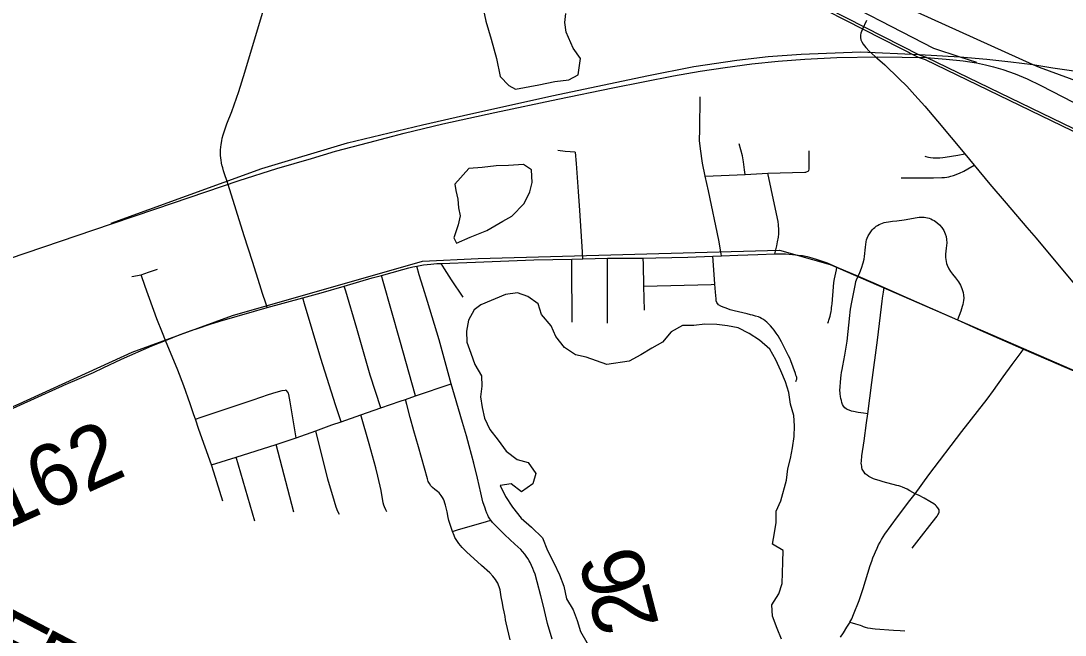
# Model space of a CAD drawing. Extents: x 0 to 34, y 0 to 22.
# Drawn here: x 3.607 to 4.562, y 14.566 to 15.128 of the extents above; entities that cross this region are included whole.
import ezdxf

# ---------------------------------------------------------------- set-up
doc = ezdxf.new("R2010")
doc.units = 0
for name, color, linetype in [('GM_X_County_Road', 7, 'Continuous'), ('GM_X_County_Road_Text', 7, 'Continuous'), ('GM_X_Major_Lake', 7, 'Continuous'), ('GM_X_Minor_Lake', 7, 'Continuous'), ('GM_X_Rail_Line', 7, 'Continuous'), ('GM_X_Township_Road', 7, 'Continuous'), ('GM_X_Township_Road_Text', 7, 'Continuous')]:
    doc.layers.add(name, color=color, linetype=linetype)

msp = doc.modelspace()

# ---------------------------------------------------------------- linework, layer by layer
at = {"layer": 'GM_X_County_Road'}
for p, q in [((4.47048, 15.00593), (4.47909, 14.99559)), ((4.11119, 14.90945), (4.1212, 14.90973)), ((4.1212, 14.90973), (4.14376, 14.91036)), ((4.24024, 14.91223), (4.24809, 14.91252)), ((4.35362, 14.9022), (4.37305, 14.89396)), ((3.83265, 14.86521), (3.86518, 14.87421))]:
    msp.add_line(p, q, dxfattribs=at)
for points in [[(3.79142, 14.99481), (3.79119, 14.99568), (3.79081, 14.99776), (3.79038, 15.00004), (3.79017, 15.00236), (3.78998, 15.00446), (3.78999, 15.00705), (3.78999, 15.00951), (3.79014, 15.0119), (3.79046, 15.01455), (3.79106, 15.01773), (3.79151, 15.02013), (3.79238, 15.02325), (3.79319, 15.02618), (3.79571, 15.03324), (3.80011, 15.04462), (3.80658, 15.06305), (3.81213, 15.08062), (3.82285, 15.11626), (3.83435, 15.155)], [(4.38074, 15.12777), (4.37658, 15.11939), (4.37548, 15.11633), (4.37516, 15.11435), (4.37517, 15.11233), (4.37557, 15.11034), (4.37632, 15.10847), (4.37767, 15.10622), (4.37872, 15.1048), (4.38004, 15.10321), (4.38306, 15.09997), (4.38863, 15.0949), (4.39079, 15.093)], [(4.39079, 15.093), (4.39729, 15.08728), (4.41037, 15.07499), (4.41749, 15.06777), (4.42482, 15.05954), (4.43393, 15.04946), (4.44559, 15.03592), (4.47048, 15.00593)], [(3.83265, 14.86521), (3.83123, 14.86942), (3.82833, 14.87803), (3.82579, 14.88618), (3.81911, 14.90734), (3.81157, 14.93103), (3.79688, 14.97783), (3.79265, 14.99021), (3.79189, 14.99307), (3.79142, 14.99481)], [(4.47909, 14.99559), (4.49344, 14.97805), (4.50846, 14.96076), (4.52735, 14.93848), (4.53589, 14.92867), (4.57818, 14.87774), (4.58016, 14.87529)], [(3.99169, 14.90565), (4.02318, 14.90694), (4.05351, 14.90812), (4.07639, 14.90886), (4.11119, 14.90945)], [(4.14376, 14.91036), (4.16297, 14.91043), (4.17644, 14.91057)], [(4.17644, 14.91057), (4.18814, 14.91068), (4.2173, 14.91143), (4.24024, 14.91223)], [(4.24809, 14.91252), (4.26293, 14.91306), (4.28133, 14.91382), (4.29682, 14.91438)], [(4.29682, 14.91438), (4.30082, 14.91452), (4.30668, 14.91436), (4.31293, 14.91394), (4.31816, 14.91333), (4.32215, 14.91278), (4.32632, 14.91203), (4.33062, 14.91089), (4.3347, 14.90965), (4.34468, 14.90606), (4.35362, 14.9022)], [(3.93697, 14.89472), (3.95673, 14.9002), (3.96196, 14.90153), (3.96583, 14.90243), (3.96928, 14.90321)], [(3.96928, 14.90321), (3.97549, 14.90432), (3.98211, 14.90505), (3.98758, 14.90549), (3.99169, 14.90565)], [(3.90301, 14.88495), (3.92849, 14.89231), (3.93697, 14.89472)], [(4.37305, 14.89396), (4.38862, 14.88712), (4.39678, 14.88348)], [(3.86518, 14.87421), (3.88205, 14.87887), (3.90301, 14.88495)], [(4.39678, 14.88348), (4.41871, 14.87372), (4.45633, 14.85736), (4.46384, 14.854)], [(3.73951, 14.83523), (3.74619, 14.8379), (3.75306, 14.84051), (3.76294, 14.84416), (3.76966, 14.84651), (3.78047, 14.84999), (3.78938, 14.85277), (3.82102, 14.86183), (3.83265, 14.86521)], [(4.46384, 14.854), (4.4847, 14.84468), (4.52428, 14.82727)], [(3.60028, 14.7732), (3.62629, 14.78512), (3.6454, 14.79372), (3.64705, 14.79444), (3.64812, 14.79486), (3.6509, 14.79607), (3.65883, 14.79955), (3.67358, 14.8059), (3.6825, 14.81022), (3.69926, 14.81804), (3.72708, 14.83014), (3.73409, 14.83306), (3.73951, 14.83523)], [(4.52428, 14.82727), (4.53136, 14.82416), (4.54884, 14.81645)], [(4.54884, 14.81645), (4.56098, 14.81121), (4.57244, 14.80649), (4.58069, 14.80325), (4.58417, 14.80188), (4.60302, 14.79528), (4.61965, 14.79024), (4.65665, 14.78009)]]:
    msp.add_lwpolyline(points, dxfattribs=at)
at = {"layer": 'GM_X_Major_Lake'}
msp.add_line((4.05044, 14.87717), (4.0278, 14.8679), dxfattribs=at)
for points in [[(4.30307, 14.56171), (4.29883, 14.57154), (4.29458, 14.58289), (4.29412, 14.59312), (4.30047, 14.60341), (4.30343, 14.61292), (4.30373, 14.6224), (4.30403, 14.63226), (4.30433, 14.64289), (4.29482, 14.64888), (4.29663, 14.65913), (4.29807, 14.66863), (4.29799, 14.67886), (4.30246, 14.68838), (4.30761, 14.70738), (4.30867, 14.71763), (4.31124, 14.72713), (4.31306, 14.73701), (4.31449, 14.74726), (4.3148, 14.75712), (4.31435, 14.7666), (4.31124, 14.77682), (4.30964, 14.78742), (4.30654, 14.79726), (4.30229, 14.80746), (4.29768, 14.81729), (4.2923, 14.82711), (4.28277, 14.83538), (4.27326, 14.84137), (4.26338, 14.8466), (4.25353, 14.84842), (4.24368, 14.84986), (4.2327, 14.85015), (4.22287, 14.84894), (4.21227, 14.84886), (4.2021, 14.84309), (4.19422, 14.83354), (4.18442, 14.82816), (4.17425, 14.82201), (4.1637, 14.81624), (4.14329, 14.81305), (4.12431, 14.81973), (4.11445, 14.82192), (4.10456, 14.82867), (4.09653, 14.83885), (4.09229, 14.84868), (4.08351, 14.85885), (4.0804, 14.86868), (4.07089, 14.87544), (4.0614, 14.87878), (4.05044, 14.87717)], [(4.0278, 14.8679), (4.02178, 14.8633), (4.01655, 14.85378), (4.01474, 14.84352), (4.0152, 14.83367), (4.01868, 14.82345), (4.02255, 14.81324), (4.02869, 14.80267), (4.02876, 14.79319), (4.0277, 14.7837), (4.02929, 14.77385), (4.03126, 14.76401), (4.03626, 14.75381), (4.0439, 14.744), (4.05117, 14.73382), (4.06107, 14.72631), (4.07131, 14.72336), (4.0782, 14.71355), (4.07562, 14.70405), (4.06508, 14.69676), (4.05557, 14.7039), (4.04574, 14.7023), (4.05036, 14.69248), (4.05687, 14.68267), (4.0649, 14.67249), (4.07442, 14.66422)], [(4.07442, 14.66422), (4.08434, 14.65444), (4.08897, 14.64309), (4.09473, 14.63176), (4.09974, 14.6208), (4.10398, 14.61022), (4.10634, 14.59886), (4.11248, 14.58866), (4.11596, 14.57883), (4.11906, 14.569), (4.12482, 14.5588), (4.1302, 14.54898), (4.13141, 14.53837), (4.12808, 14.52886), (4.12248, 14.51934), (4.11081, 14.51128), (4.10063, 14.50589), (4.09045, 14.50012), (4.08107, 14.49057), (4.07849, 14.48107), (4.08122, 14.47123), (4.08622, 14.46065), (4.09538, 14.45048), (4.10227, 14.44029)]]:
    msp.add_lwpolyline(points, dxfattribs=at)
at = {"layer": 'GM_X_Minor_Lake'}
msp.add_line((4.01699, 14.99259), (4.00423, 14.97807), dxfattribs=at)
for points in [[(4.02866, 15.14589), (4.03259, 15.12734), (4.03726, 15.11069), (4.04232, 15.09328), (4.04548, 15.07662), (4.05349, 15.06834), (4.05957, 15.06497), (4.08112, 15.06893), (4.09547, 15.07208), (4.10833, 15.0737), (4.117, 15.07832), (4.11915, 15.09312), (4.11227, 15.10255), (4.1061, 15.11729), (4.1049, 15.126), (4.10559, 15.13435)], [(4.00423, 14.97807), (4.00504, 14.97239), (4.00699, 14.96444), (4.00743, 14.95648), (4.009, 14.94929), (4.00717, 14.94093), (4.0031, 14.92914), (4.00579, 14.92423), (4.01824, 14.92964), (4.03333, 14.93582), (4.04802, 14.94428), (4.05631, 14.9489), (4.06758, 14.96036), (4.0728, 14.97102), (4.075, 14.97976), (4.07415, 14.99113), (4.06692, 14.99601), (4.0533, 14.99514), (4.04195, 14.99505), (4.02909, 14.99344), (4.01699, 14.99259)]]:
    msp.add_lwpolyline(points, dxfattribs=at)
at = {"layer": 'GM_X_Rail_Line'}
for p, q in [((4.42904, 15.09676), (4.46599, 15.09465)), ((4.46599, 15.09465), (4.48118, 15.08977))]:
    msp.add_line(p, q, dxfattribs=at)
for points in [[(3.62916, 15.49068), (3.68617, 15.47834), (3.72717, 15.4655), (3.77223, 15.44299), (3.83301, 15.41673), (3.98419, 15.34106), (4.12283, 15.26764), (4.44196, 15.10258), (4.46599, 15.09465)], [(4.24098, 15.21994), (4.53283, 15.0878)], [(4.99295, 14.82402), (4.43543, 15.09396), (4.42924, 15.09621), (4.34594, 15.13852)], [(4.99193, 14.82192), (4.43451, 15.09181), (4.42831, 15.09406), (4.34487, 15.13645)], [(3.68997, 14.94247), (3.82759, 14.99252), (3.90614, 15.01596), (3.97471, 15.03258), (4.01885, 15.04243), (4.09449, 15.05926), (4.17979, 15.07742), (4.22279, 15.08576), (4.26215, 15.09171), (4.29084, 15.09504), (4.32093, 15.09714), (4.37516, 15.09923), (4.42904, 15.09676)], [(3.50247, 14.87812), (3.69017, 14.94192), (3.73066, 14.95558), (3.80696, 14.9814), (3.84128, 14.9924), (3.87294, 15.00156), (3.8951, 15.00823), (3.92559, 15.01639), (3.95774, 15.02472), (3.99306, 15.03322), (4.04088, 15.04371), (4.09844, 15.05589), (4.14868, 15.06621), (4.20416, 15.07737), (4.22865, 15.0817), (4.25147, 15.08503), (4.2758, 15.0882), (4.29996, 15.0907), (4.32428, 15.09253), (4.3536, 15.0942), (4.39092, 15.0947), (4.43543, 15.09396), (4.45359, 15.09257), (4.46909, 15.09109), (4.48139, 15.08922), (4.48936, 15.08742), (4.49688, 15.08564), (4.5055, 15.08304), (4.51658, 15.07908), (4.52752, 15.07443), (4.54024, 15.06855), (4.80744, 14.93059)], [(4.46599, 15.09465), (4.49059, 15.09244), (4.51269, 15.09016), (4.53283, 15.0878)], [(4.53283, 15.0878), (4.53861, 15.08519), (4.62419, 15.05393), (4.66489, 15.03324), (4.83287, 14.93429), (4.87459, 14.9101), (4.91109, 14.88847), (4.9361, 14.87045), (4.96181, 14.85192)], [(4.53283, 15.0878), (4.551, 15.08447), (4.58766, 15.07934)], [(3.17568, 14.58644), (3.60559, 14.77702), (3.70895, 14.82435), (3.80076, 14.85805), (3.97456, 14.90768), (4.0254, 14.91006), (4.30098, 14.91785), (4.34732, 14.90477), (4.58234, 14.80243), (4.75168, 14.75729), (4.9245, 14.7137), (5.0662, 14.68464), (5.22516, 14.67921), (5.29626, 14.6779)]]:
    msp.add_lwpolyline(points, dxfattribs=at)
at = {"layer": 'GM_X_Township_Road'}
for p, q in [((4.23326, 14.98535), (4.26958, 14.98714)), ((4.26958, 14.98714), (4.29045, 14.98812)), ((4.17772, 14.86274), (4.17714, 14.88469)), ((3.96821, 14.78447), (4.00078, 14.7954)), ((3.95892, 14.78116), (3.96821, 14.78447)), ((3.90009, 14.76079), (3.91818, 14.76708)), ((3.91818, 14.76708), (3.93646, 14.77342)), ((3.8407, 14.74007), (3.8591, 14.74607)), ((3.8591, 14.74607), (3.87693, 14.7526)), ((3.80424, 14.72834), (3.8407, 14.74007)), ((3.85704, 14.67799), (3.8407, 14.74007)), ((3.78148, 14.72136), (3.80424, 14.72834)), ((3.82118, 14.66987), (3.80424, 14.72834))]:
    msp.add_line(p, q, dxfattribs=at)
for points in [[(4.23326, 14.98535), (4.23062, 14.99751), (4.2287, 15.01044), (4.22805, 15.01825), (4.22813, 15.0282), (4.22847, 15.05805)], [(4.26958, 14.98714), (4.26907, 14.99126), (4.26817, 14.99858), (4.26711, 15.00401), (4.26409, 15.01521)], [(4.11433, 15.00744), (4.10513, 15.00802), (4.0984, 15.00899)], [(4.1212, 14.90973), (4.12081, 14.91625), (4.1186, 14.95412), (4.11736, 14.97147), (4.11535, 14.99696), (4.11451, 15.00743)], [(4.32791, 14.99059), (4.32815, 14.99175), (4.32817, 14.99238), (4.32809, 15.00853)], [(4.43389, 15.00385), (4.43502, 15.00339), (4.43725, 15.00288), (4.43932, 15.00263), (4.44162, 15.00239), (4.44415, 15.00226), (4.44598, 15.00227), (4.44784, 15.00229), (4.45034, 15.0025), (4.45274, 15.00278), (4.46415, 15.00462), (4.47048, 15.00593)], [(4.41249, 14.98405), (4.42526, 14.98404), (4.44185, 14.9841), (4.4496, 14.98427), (4.45191, 14.9844), (4.45421, 14.98458), (4.4559, 14.98488), (4.45784, 14.98536), (4.46015, 14.98621), (4.46564, 14.98822), (4.46962, 14.99003), (4.4734, 14.99225), (4.47909, 14.99559)], [(4.24809, 14.91252), (4.24773, 14.91447), (4.24549, 14.927), (4.23611, 14.97219), (4.23326, 14.98535)], [(4.29045, 14.98812), (4.32421, 14.98917), (4.32523, 14.98923), (4.32593, 14.98936), (4.32745, 14.98994), (4.32791, 14.99056)], [(4.29682, 14.91438), (4.29855, 14.92166), (4.29941, 14.92527), (4.30005, 14.92956), (4.30046, 14.93277), (4.30054, 14.9363), (4.30022, 14.94091), (4.29973, 14.94412), (4.29657, 14.95969), (4.29045, 14.98812)], [(4.37305, 14.89396), (4.37457, 14.89733), (4.37609, 14.90117), (4.3777, 14.90619), (4.37845, 14.90953), (4.37885, 14.91188), (4.37967, 14.92048), (4.38036, 14.92549), (4.38074, 14.92714), (4.38119, 14.92861), (4.38222, 14.931), (4.38389, 14.93377), (4.38588, 14.9363), (4.38705, 14.9375), (4.38819, 14.93856), (4.38954, 14.93963), (4.39081, 14.94048), (4.39214, 14.94131), (4.39366, 14.942), (4.39515, 14.94258), (4.39697, 14.9431), (4.39868, 14.94345), (4.40067, 14.94376), (4.40453, 14.94416), (4.40854, 14.9445), (4.41525, 14.94542), (4.42685, 14.94759), (4.42887, 14.94789), (4.43077, 14.94802), (4.43328, 14.94796), (4.43489, 14.94777), (4.43656, 14.94742), (4.43806, 14.9469), (4.43954, 14.9463), (4.44101, 14.94562), (4.44242, 14.94485), (4.44379, 14.94395), (4.44509, 14.94304), (4.44751, 14.94089), (4.4496, 14.93843), (4.45135, 14.93572), (4.45273, 14.93278), (4.45347, 14.93029), (4.45387, 14.92761), (4.45399, 14.92451), (4.45362, 14.91947), (4.45301, 14.91398), (4.45304, 14.91108), (4.4532, 14.90924), (4.45347, 14.90743), (4.45389, 14.90566), (4.45442, 14.90396), (4.45583, 14.90066), (4.45734, 14.89811), (4.45922, 14.89581), (4.46214, 14.89252), (4.46474, 14.88891), (4.46665, 14.8856), (4.46794, 14.88267), (4.46904, 14.87898), (4.46947, 14.87645), (4.46963, 14.87374), (4.46944, 14.87182), (4.46916, 14.86996), (4.46874, 14.86794), (4.46827, 14.86621), (4.46683, 14.86187), (4.46384, 14.854)], [(4.11138, 14.85204), (4.11121, 14.9041), (4.11119, 14.90945)], [(4.14387, 14.85104), (4.14377, 14.90515), (4.14376, 14.91036)], [(4.17714, 14.88469), (4.1766, 14.90463), (4.17644, 14.91057)], [(4.31597, 14.79769), (4.31645, 14.7984), (4.31678, 14.79911), (4.31698, 14.79986), (4.31681, 14.80124), (4.3166, 14.80204), (4.31611, 14.80344), (4.31558, 14.80497), (4.3114, 14.81665), (4.31041, 14.81898), (4.30945, 14.82123), (4.303, 14.834), (4.30143, 14.83663), (4.2998, 14.83936), (4.29801, 14.84194), (4.29622, 14.84451), (4.29468, 14.84636), (4.29298, 14.84839), (4.29081, 14.85057), (4.28941, 14.85198), (4.28793, 14.85318), (4.28642, 14.85442), (4.28474, 14.85538), (4.28325, 14.85602), (4.28181, 14.85665), (4.27925, 14.85744), (4.27638, 14.85833), (4.27469, 14.85873), (4.27155, 14.85948), (4.25962, 14.86226), (4.25606, 14.8632), (4.2523, 14.8646), (4.24946, 14.8657), (4.24749, 14.86643), (4.24537, 14.86773), (4.24372, 14.86984), (4.24324, 14.8714), (4.24306, 14.87314), (4.24257, 14.87935), (4.2421, 14.88653), (4.24051, 14.90841), (4.24024, 14.91223)], [(3.70867, 14.89365), (3.71714, 14.8951), (3.72407, 14.89762), (3.73234, 14.90048)], [(4.09304, 14.56192), (4.089, 14.57621), (4.08512, 14.59191), (4.08273, 14.60157), (4.07959, 14.61419), (4.07751, 14.62129), (4.07653, 14.62395), (4.07561, 14.62648), (4.07429, 14.62938), (4.07308, 14.63206), (4.07225, 14.63349), (4.07094, 14.63573), (4.06953, 14.63767), (4.06808, 14.63967), (4.06605, 14.64197), (4.06443, 14.64379), (4.06171, 14.64637), (4.05906, 14.64888), (4.04996, 14.65738), (4.04016, 14.66693), (4.03855, 14.6686), (4.03701, 14.67068), (4.03607, 14.67199), (4.03507, 14.67368), (4.03427, 14.67527), (4.03356, 14.67701), (4.0326, 14.67959), (4.03182, 14.68167), (4.02992, 14.68741), (4.02789, 14.69588), (4.0249, 14.70919), (4.02163, 14.72302), (4.01738, 14.73881), (4.0147, 14.748), (4.01114, 14.76018), (4.0039, 14.78503), (4.00078, 14.7954), (3.98973, 14.83567), (3.97918, 14.87066), (3.97519, 14.88355), (3.97165, 14.89532), (3.96928, 14.90321)], [(4.01166, 14.87483), (4.00102, 14.89049), (3.99474, 14.90061), (3.99169, 14.90565)], [(4.34534, 14.85095), (4.34578, 14.85235), (4.34617, 14.85359), (4.34678, 14.85557), (4.34734, 14.85725), (4.34778, 14.85894), (4.34829, 14.86175), (4.34855, 14.86356), (4.34878, 14.86525), (4.34903, 14.86698), (4.34925, 14.86856), (4.35046, 14.88412), (4.35085, 14.88826), (4.35144, 14.89155), (4.35312, 14.89974), (4.35362, 14.9022)], [(3.73951, 14.83523), (3.73685, 14.84199), (3.73175, 14.85491), (3.72088, 14.88465), (3.71714, 14.8951)], [(3.96821, 14.78447), (3.95375, 14.83552), (3.93857, 14.88908), (3.93697, 14.89472)], [(4.38183, 14.76812), (4.37796, 14.76861), (4.37309, 14.76924), (4.36885, 14.77007), (4.36684, 14.77056), (4.36476, 14.77123), (4.36305, 14.7721), (4.36192, 14.77273), (4.36092, 14.77357), (4.35958, 14.77515), (4.35883, 14.77666), (4.35808, 14.77835), (4.35765, 14.78007), (4.35717, 14.78197), (4.35684, 14.784), (4.35648, 14.78621), (4.35643, 14.78742), (4.35637, 14.78914), (4.35709, 14.80068), (4.35735, 14.80344), (4.35776, 14.80569), (4.35837, 14.80864), (4.35905, 14.81193), (4.36096, 14.82164), (4.36308, 14.83454), (4.36547, 14.85805), (4.3658, 14.86116), (4.36613, 14.86367), (4.36642, 14.86545), (4.36705, 14.86866), (4.36856, 14.87642), (4.37048, 14.88686), (4.37097, 14.88896), (4.37159, 14.8907), (4.37305, 14.89396)], [(3.93646, 14.77342), (3.92668, 14.80342), (3.9144, 14.84612), (3.90442, 14.88011), (3.90301, 14.88495)], [(4.17714, 14.88469), (4.23865, 14.88643), (4.2421, 14.88653)], [(4.42503, 14.69491), (4.42041, 14.69752), (4.41787, 14.69895), (4.41566, 14.70004), (4.4137, 14.70088), (4.41193, 14.70146), (4.41019, 14.70205), (4.40846, 14.70256), (4.39596, 14.70593), (4.39226, 14.70697), (4.38878, 14.70802), (4.38692, 14.70865), (4.38458, 14.70973), (4.38267, 14.71082), (4.38116, 14.7119), (4.37958, 14.71324), (4.37843, 14.71459), (4.37732, 14.71633), (4.37683, 14.71741), (4.3765, 14.71891), (4.37625, 14.72008), (4.37608, 14.72142), (4.37591, 14.72292), (4.37594, 14.72464), (4.37637, 14.7297), (4.37845, 14.74321), (4.38078, 14.75982), (4.38183, 14.76812), (4.38544, 14.79668), (4.39068, 14.83528), (4.39442, 14.86607), (4.39475, 14.86874), (4.395, 14.87074), (4.39542, 14.874), (4.39618, 14.87926), (4.39678, 14.88348)], [(3.90009, 14.76079), (3.89495, 14.77615), (3.88174, 14.81875), (3.86679, 14.86859), (3.86518, 14.87421)], [(3.7669, 14.7631), (3.76551, 14.76711), (3.76211, 14.7771), (3.75628, 14.79351), (3.75083, 14.8081), (3.73951, 14.83523)], [(4.35673, 14.56363), (4.35951, 14.56766), (4.3628, 14.57297), (4.36498, 14.57648), (4.36557, 14.57753), (4.36718, 14.58041), (4.36891, 14.58434), (4.37391, 14.59737), (4.37752, 14.60806), (4.38394, 14.6291), (4.38541, 14.63326), (4.38641, 14.63611), (4.38783, 14.63951), (4.38881, 14.64186), (4.39029, 14.64507), (4.39168, 14.64811), (4.39306, 14.65059), (4.39442, 14.65305), (4.39755, 14.65776), (4.40915, 14.67392), (4.42043, 14.6888), (4.42503, 14.69491), (4.43776, 14.71211), (4.46781, 14.75179), (4.49099, 14.78141), (4.49677, 14.78937), (4.50554, 14.80185), (4.51399, 14.81316), (4.522, 14.82414), (4.52428, 14.82727)], [(3.7669, 14.7631), (3.7722, 14.765), (3.81971, 14.78091), (3.83379, 14.78571), (3.84088, 14.78795), (3.84621, 14.78943), (3.84896, 14.78975)], [(3.8591, 14.74607), (3.85817, 14.75169), (3.85365, 14.77905), (3.85232, 14.7857), (3.85191, 14.78704), (3.85112, 14.78823), (3.85007, 14.78923), (3.84896, 14.78975)], [(3.93646, 14.77342), (3.95416, 14.77958), (3.95892, 14.78116)], [(4.00198, 14.66035), (4.00069, 14.66409), (3.99946, 14.66774), (3.9988, 14.67032), (3.99808, 14.67307), (3.99713, 14.67838), (3.99577, 14.68443), (3.99514, 14.68636), (3.99442, 14.68854), (3.99388, 14.69002), (3.99298, 14.69161), (3.99178, 14.6934), (3.99078, 14.69449), (3.98969, 14.69569), (3.98821, 14.69698), (3.98582, 14.69888), (3.98373, 14.70047), (3.98218, 14.70217), (3.98085, 14.70425), (3.97985, 14.70625), (3.9791, 14.70849), (3.97085, 14.73771), (3.96654, 14.75253), (3.96326, 14.76458), (3.96014, 14.7765), (3.95892, 14.78116)], [(3.94197, 14.67827), (3.94107, 14.68031), (3.93991, 14.68288), (3.9393, 14.68449), (3.93876, 14.68663), (3.93674, 14.69776), (3.93384, 14.71113), (3.93196, 14.71857), (3.92577, 14.74058), (3.91818, 14.76708)], [(3.78148, 14.72136), (3.77015, 14.75368), (3.7669, 14.7631)], [(3.87693, 14.7526), (3.89156, 14.75783), (3.90009, 14.76079)], [(3.89858, 14.67586), (3.89724, 14.67863), (3.89563, 14.6826), (3.89401, 14.68792), (3.88815, 14.7083), (3.87693, 14.7526)], [(3.79185, 14.68804), (3.7838, 14.71475), (3.78148, 14.72136)], [(4.42253, 14.64506), (4.42875, 14.65321), (4.44063, 14.66858), (4.44526, 14.67445), (4.44599, 14.67547), (4.44657, 14.6765), (4.44708, 14.67806), (4.44717, 14.67938), (4.44699, 14.68016), (4.44653, 14.68116), (4.44593, 14.68195), (4.4454, 14.68261), (4.44474, 14.68341), (4.44367, 14.68437), (4.4421, 14.68559), (4.43857, 14.68792), (4.43345, 14.691), (4.4289, 14.69327), (4.42503, 14.69491)], [(4.00198, 14.66035), (4.00665, 14.66173), (4.03314, 14.66954), (4.03701, 14.67068)], [(4.05485, 14.56134), (4.05116, 14.57674), (4.05063, 14.57961), (4.0502, 14.58245), (4.04916, 14.58676), (4.0485, 14.59084), (4.04767, 14.59465), (4.04658, 14.60063), (4.04549, 14.607), (4.04476, 14.60977), (4.0441, 14.61138), (4.04334, 14.6132), (4.04234, 14.61482), (4.04137, 14.61639), (4.03906, 14.61936), (4.03609, 14.62253), (4.0287, 14.62918), (4.01482, 14.6416), (4.01093, 14.6456), (4.0078, 14.64943), (4.00546, 14.65295), (4.00431, 14.65498), (4.00345, 14.65677), (4.00198, 14.66035)], [(4.36557, 14.57753), (4.37075, 14.57592), (4.37486, 14.57464), (4.37642, 14.57398), (4.37773, 14.57336), (4.37941, 14.57273), (4.38147, 14.57226), (4.38422, 14.57178), (4.38627, 14.57148), (4.38848, 14.57117), (4.40521, 14.57003), (4.41136, 14.56964), (4.41566, 14.56941)]]:
    msp.add_lwpolyline(points, dxfattribs=at)

# ---------------------------------------------------------------- texts
at = {"layer": 'GM_X_County_Road_Text'}
msp.add_text('C-162', height=0.056818, rotation=24.35303, dxfattribs=at).set_placement((3.51718, 14.62709))
at = {"layer": 'GM_X_Township_Road_Text'}
for s, rotation, p in [('6', 104.77015, (4.18242, 14.60933)), ('2', 104.48251, (4.19125, 14.57514)), ('E', 332.31001, (3.56689, 14.54239)), ('R', 332.32255, (3.60454, 14.52263))]:
    msp.add_text(s, height=0.05682, rotation=rotation, dxfattribs=at).set_placement(p)

doc.saveas('drawing.dxf')
